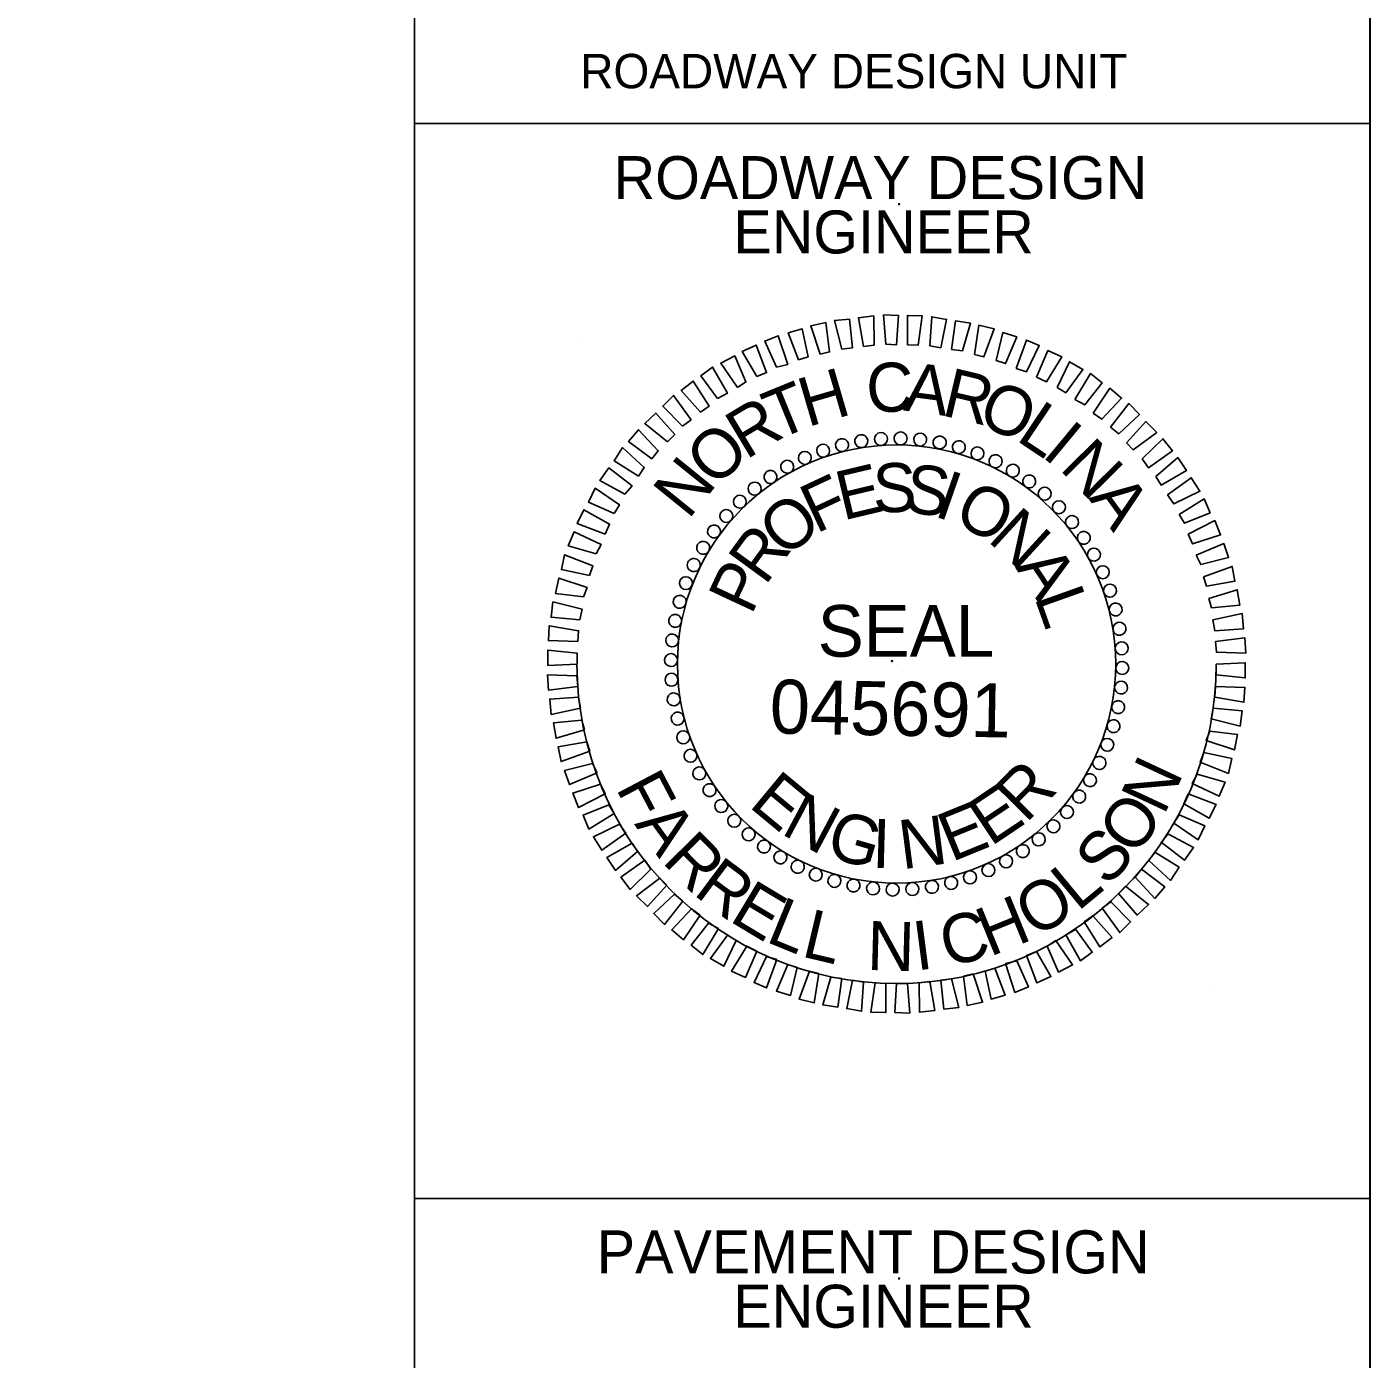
# Model space of a CAD drawing. Extents: x 0 to 3.05, y 0 to 1.83.
# Drawn here: x 2.5366 to 2.7708, y 1.3705 to 1.6029 of the extents above; entities that cross this region are included whole.
import ezdxf

# ---------------------------------------------------------------- set-up
doc = ezdxf.new("R2010")
doc.units = 0
for name, color, linetype in [('Draft_Construction', 7, 'Continuous'), ('Scratch_Level_1', 7, 'Continuous'), ('Scratch_Level_5', 7, 'Continuous'), ('Sheet Border Standard 30in CELL', 7, 'Continuous'), ('Sheet_PE_Note_CELL', 7, 'Continuous'), ('Sheet_Plan_CELL', 7, 'Continuous')]:
    doc.layers.add(name, color=color, linetype=linetype)

msp = doc.modelspace()

# ---------------------------------------------------------------- linework, layer by layer
at = {"layer": 'Draft_Construction'}
for radius, start, end in [(0.03822, 0, 180), (0.05574, 180, 0), (0.03822, 180, 0)]:
    msp.add_arc((2.68825, 1.49175), radius, start, end, dxfattribs=at)
at = {"layer": 'Scratch_Level_1'}
for p, q in [((2.60412, 0.0625), (2.60416, 1.77083)), ((2.77079, 0.0625), (2.77083, 1.77083))]:
    msp.add_line(p, q, dxfattribs=at)
msp.add_lwpolyline([(2.77079, 0.0625), (0.0625, 0.0625), (0.0625, 1.77083), (2.77079, 1.77083)], close=True, dxfattribs=at)
at = {"layer": 'Scratch_Level_5'}
for p, q in [((2.6334, 1.5489), (2.6334, 1.5489)), ((2.7431, 1.4346), (2.7431, 1.4346))]:
    msp.add_line(p, q, dxfattribs=at)
for centre in [(2.6887, 1.57195), (2.68745, 1.49226), (2.68745, 1.49226), (2.68745, 1.49226), (2.68869, 1.38457)]:
    msp.add_circle(centre, 0.0001, dxfattribs=at)
at = {"layer": 'Sheet_PE_Note_CELL'}
for p, q in [((2.67868, 1.52996), (2.67868, 1.52996)), ((2.68213, 1.53058), (2.68213, 1.53058)), ((2.68551, 1.53105), (2.68551, 1.53105)), ((2.68896, 1.53113), (2.68896, 1.53113)), ((2.69241, 1.5309), (2.69241, 1.5309)), ((2.69578, 1.53035), (2.69578, 1.53035)), ((2.67225, 1.52776), (2.67225, 1.52776)), ((2.67538, 1.52901), (2.67538, 1.52901)), ((2.69908, 1.52964), (2.69908, 1.52964)), ((2.70237, 1.52854), (2.70237, 1.52854)), ((2.66919, 1.52619), (2.66919, 1.52619)), ((2.70551, 1.52713), (2.70551, 1.52713)), ((2.70857, 1.52556), (2.70857, 1.52556)), ((2.66621, 1.52439), (2.66621, 1.52439)), ((2.7114, 1.5236), (2.7114, 1.5236)), ((2.66346, 1.52242), (2.66346, 1.52242)), ((2.71414, 1.52148), (2.71414, 1.52148)), ((2.66087, 1.52007), (2.66087, 1.52007)), ((2.71657, 1.51913), (2.71657, 1.51913)), ((2.65852, 1.51764), (2.65852, 1.51764)), ((2.71893, 1.51654), (2.71893, 1.51654)), ((2.6564, 1.51489), (2.6564, 1.51489)), ((2.72089, 1.51379), (2.72089, 1.51379)), ((2.65444, 1.51207), (2.65444, 1.51207)), ((2.65287, 1.50901), (2.65287, 1.50901)), ((2.72269, 1.51081), (2.72269, 1.51081)), ((2.72426, 1.50775), (2.72426, 1.50775)), ((2.65146, 1.50587), (2.65146, 1.50587)), ((2.72552, 1.50462), (2.72552, 1.50462)), ((2.65036, 1.50258), (2.65036, 1.50258)), ((2.64965, 1.49928), (2.64965, 1.49928)), ((2.72646, 1.50132), (2.72646, 1.50132)), ((2.72709, 1.49787), (2.72709, 1.49787)), ((2.6491, 1.49591), (2.6491, 1.49591)), ((2.64887, 1.49245), (2.64887, 1.49245)), ((2.72756, 1.49449), (2.72756, 1.49449)), ((2.68825, 1.49175), (2.68825, 1.49175)), ((2.72764, 1.49104), (2.72764, 1.49104)), ((2.64895, 1.489), (2.64895, 1.489)), ((2.7274, 1.48759), (2.7274, 1.48759)), ((2.64942, 1.48563), (2.64942, 1.48563)), ((2.72685, 1.48422), (2.72685, 1.48422)), ((2.65004, 1.48218), (2.65004, 1.48218)), ((2.72614, 1.48092), (2.72614, 1.48092)), ((2.65099, 1.47888), (2.65099, 1.47888)), ((2.72505, 1.47763), (2.72505, 1.47763)), ((2.65224, 1.47574), (2.65224, 1.47574)), ((2.72363, 1.47449), (2.72363, 1.47449)), ((2.65381, 1.47268), (2.65381, 1.47268)), ((2.72207, 1.47143), (2.72207, 1.47143)), ((2.65561, 1.4697), (2.65561, 1.4697)), ((2.65758, 1.46696), (2.65758, 1.46696)), ((2.7201, 1.4686), (2.7201, 1.4686)), ((2.65993, 1.46437), (2.65993, 1.46437)), ((2.71799, 1.46586), (2.71799, 1.46586)), ((2.66236, 1.46201), (2.66236, 1.46201)), ((2.71563, 1.46343), (2.71563, 1.46343)), ((2.66511, 1.4599), (2.66511, 1.4599)), ((2.71304, 1.46107), (2.71304, 1.46107)), ((2.66793, 1.45793), (2.66793, 1.45793)), ((2.70732, 1.45731), (2.70732, 1.45731)), ((2.7103, 1.45911), (2.7103, 1.45911)), ((2.67099, 1.45637), (2.67099, 1.45637)), ((2.67413, 1.45495), (2.67413, 1.45495)), ((2.70426, 1.45574), (2.70426, 1.45574)), ((2.67742, 1.45386), (2.67742, 1.45386)), ((2.68072, 1.45315), (2.68072, 1.45315)), ((2.68409, 1.4526), (2.68409, 1.4526)), ((2.691, 1.45244), (2.691, 1.45244)), ((2.69437, 1.45291), (2.69437, 1.45291)), ((2.69782, 1.45354), (2.69782, 1.45354)), ((2.70112, 1.45448), (2.70112, 1.45448)), ((2.68754, 1.45236), (2.68754, 1.45236))]:
    msp.add_line(p, q, dxfattribs=at)
for points in [[(2.67491, 1.5458), (2.67327, 1.55075), (2.67593, 1.5513), (2.67656, 1.5462)], [(2.67868, 1.54667), (2.67742, 1.55169), (2.68001, 1.55192), (2.68056, 1.5469)], [(2.68245, 1.54714), (2.68158, 1.55216), (2.68425, 1.55247), (2.68433, 1.54737)], [(2.68637, 1.54753), (2.68598, 1.55263), (2.68856, 1.55255), (2.68825, 1.54745)], [(2.69013, 1.54745), (2.69013, 1.55255), (2.69272, 1.55247), (2.69202, 1.54737)], [(2.69406, 1.54722), (2.69437, 1.55232), (2.69696, 1.55185), (2.69594, 1.5469)], [(2.69782, 1.54659), (2.69853, 1.55161), (2.70112, 1.55122), (2.69971, 1.54635)], [(2.70182, 1.54573), (2.70261, 1.55083), (2.70528, 1.5502), (2.70347, 1.54533)], [(2.6673, 1.54353), (2.66526, 1.54808), (2.66762, 1.54902), (2.66927, 1.544)], [(2.67115, 1.54478), (2.66934, 1.54949), (2.67178, 1.5502), (2.6728, 1.54533)], [(2.70559, 1.54471), (2.70677, 1.54957), (2.7092, 1.54879), (2.70724, 1.54416)], [(2.66385, 1.54188), (2.66134, 1.54627), (2.66377, 1.54737), (2.66558, 1.54259)], [(2.70912, 1.54329), (2.71092, 1.54824), (2.71312, 1.54729), (2.71092, 1.54274)], [(2.71265, 1.5418), (2.71461, 1.54643), (2.71704, 1.54533), (2.71438, 1.54094)], [(2.66048, 1.54), (2.65758, 1.54423), (2.66001, 1.54549), (2.66197, 1.54094)], [(2.71626, 1.54), (2.71838, 1.54447), (2.72073, 1.54314), (2.71775, 1.53906)], [(2.65703, 1.53804), (2.65412, 1.54204), (2.65616, 1.54353), (2.65875, 1.53898)], [(2.71932, 1.53788), (2.72207, 1.54243), (2.7241, 1.54078), (2.72105, 1.53694)], [(2.65404, 1.53568), (2.65067, 1.53945), (2.65279, 1.5411), (2.65554, 1.5367)], [(2.72254, 1.53553), (2.72544, 1.53984), (2.72748, 1.53812), (2.72403, 1.53443)], [(2.65091, 1.53325), (2.64745, 1.5367), (2.64934, 1.53859), (2.6524, 1.53435)], [(2.72552, 1.53309), (2.72873, 1.53717), (2.73062, 1.53529), (2.72701, 1.53192)], [(2.64832, 1.53051), (2.64432, 1.53372), (2.64628, 1.53553), (2.64957, 1.53176)], [(2.64557, 1.52752), (2.64149, 1.53058), (2.64322, 1.53262), (2.64667, 1.52894)], [(2.72834, 1.53035), (2.73171, 1.53404), (2.7336, 1.53215), (2.72952, 1.52909)], [(2.73109, 1.52752), (2.7347, 1.53105), (2.73634, 1.52894), (2.73219, 1.52596)], [(2.64322, 1.52454), (2.63898, 1.52721), (2.64047, 1.52949), (2.64424, 1.52603)], [(2.73344, 1.52446), (2.73729, 1.52776), (2.73878, 1.52548), (2.73438, 1.52297)], [(2.64086, 1.5214), (2.63647, 1.52376), (2.63804, 1.52596), (2.64212, 1.52282)], [(2.73548, 1.52125), (2.73964, 1.52423), (2.74113, 1.52188), (2.73658, 1.51968)], [(2.63898, 1.51803), (2.63451, 1.51999), (2.63569, 1.52242), (2.63992, 1.51952)], [(2.73752, 1.5178), (2.74191, 1.52054), (2.74293, 1.51811), (2.73846, 1.51631)], [(2.63741, 1.51442), (2.63255, 1.51623), (2.63373, 1.51866), (2.6382, 1.51615)], [(2.73909, 1.51442), (2.74372, 1.51678), (2.74474, 1.51427), (2.73987, 1.5127)], [(2.63584, 1.51097), (2.63098, 1.51238), (2.632, 1.51481), (2.63671, 1.51262)], [(2.7405, 1.51073), (2.74529, 1.51277), (2.74615, 1.51034), (2.74129, 1.50909)], [(2.63467, 1.5072), (2.6298, 1.50822), (2.63035, 1.51081), (2.63529, 1.50885)], [(2.74176, 1.50697), (2.74678, 1.50877), (2.74725, 1.50618), (2.74231, 1.50532)], [(2.63365, 1.50344), (2.62878, 1.50407), (2.62933, 1.50673), (2.63427, 1.50509)], [(2.7427, 1.5032), (2.74764, 1.50469), (2.74811, 1.50203), (2.74317, 1.50156)], [(2.63302, 1.49944), (2.628, 1.49991), (2.62831, 1.50258), (2.63341, 1.50132)], [(2.7434, 1.49944), (2.7485, 1.50054), (2.74874, 1.49787), (2.74372, 1.49755)], [(2.63263, 1.49567), (2.62753, 1.49583), (2.62768, 1.49842), (2.63278, 1.49755)], [(2.74388, 1.49567), (2.74898, 1.4963), (2.74913, 1.49363), (2.74403, 1.49379)], [(2.63255, 1.49175), (2.62745, 1.49151), (2.62745, 1.49418), (2.63255, 1.49363)], [(2.74395, 1.49175), (2.74905, 1.49198), (2.74905, 1.48932), (2.74395, 1.48987)], [(2.63263, 1.48783), (2.62753, 1.4872), (2.62737, 1.48987), (2.63247, 1.48971)], [(2.74388, 1.48783), (2.74898, 1.48767), (2.74882, 1.48508), (2.74372, 1.48594)], [(2.6331, 1.48406), (2.628, 1.48296), (2.62776, 1.48563), (2.63278, 1.48594)], [(2.74348, 1.48406), (2.7485, 1.48359), (2.74819, 1.48092), (2.74309, 1.48218)], [(2.6338, 1.48029), (2.62886, 1.4788), (2.62839, 1.48147), (2.63333, 1.48194)], [(2.63474, 1.47653), (2.62972, 1.47472), (2.62925, 1.47731), (2.6342, 1.47818)], [(2.74286, 1.48006), (2.74772, 1.47943), (2.74717, 1.47676), (2.74223, 1.47841)], [(2.74184, 1.47629), (2.7467, 1.47527), (2.74615, 1.47268), (2.74121, 1.47465)], [(2.636, 1.47276), (2.63121, 1.47072), (2.63035, 1.47316), (2.63522, 1.47441)], [(2.74066, 1.47253), (2.74552, 1.47112), (2.7445, 1.46868), (2.7398, 1.47088)], [(2.63741, 1.46908), (2.63278, 1.46672), (2.63176, 1.46923), (2.63663, 1.4708)], [(2.73909, 1.46908), (2.74395, 1.46727), (2.74278, 1.46484), (2.73831, 1.46735)], [(2.63898, 1.4657), (2.63459, 1.46296), (2.63357, 1.46539), (2.63804, 1.46719)], [(2.73752, 1.46547), (2.74199, 1.46351), (2.74082, 1.46107), (2.73658, 1.46398)], [(2.64102, 1.46225), (2.63686, 1.45927), (2.63537, 1.46162), (2.63992, 1.46382)], [(2.73564, 1.46209), (2.74003, 1.45974), (2.73846, 1.45754), (2.73438, 1.46068)], [(2.64306, 1.45903), (2.63922, 1.45574), (2.63773, 1.45801), (2.64212, 1.46052)], [(2.64541, 1.45597), (2.64181, 1.45244), (2.64016, 1.45456), (2.64432, 1.45754)], [(2.73328, 1.45895), (2.73752, 1.45629), (2.73603, 1.45401), (2.73226, 1.45746)], [(2.73093, 1.45597), (2.73501, 1.45291), (2.73328, 1.45087), (2.72983, 1.45456)], [(2.64816, 1.45315), (2.64479, 1.44946), (2.6429, 1.45134), (2.64698, 1.4544)], [(2.72818, 1.45299), (2.73219, 1.44978), (2.73022, 1.44797), (2.72693, 1.45174)], [(2.65099, 1.4504), (2.64777, 1.44632), (2.64589, 1.44821), (2.64949, 1.45158)], [(2.7256, 1.45025), (2.72905, 1.44679), (2.72716, 1.44491), (2.7241, 1.44915)], [(2.65397, 1.44797), (2.65106, 1.44366), (2.64902, 1.44538), (2.65248, 1.44907)], [(2.72246, 1.44781), (2.72583, 1.44405), (2.72371, 1.4424), (2.72097, 1.44679)], [(2.65718, 1.44562), (2.65444, 1.44107), (2.6524, 1.44271), (2.65546, 1.44656)], [(2.71948, 1.44546), (2.72238, 1.44146), (2.72034, 1.43997), (2.71775, 1.44452)], [(2.66024, 1.4435), (2.65812, 1.43903), (2.65577, 1.44036), (2.65875, 1.44444)], [(2.71602, 1.4435), (2.71893, 1.43926), (2.71649, 1.43801), (2.71453, 1.44256)], [(2.66385, 1.44169), (2.66189, 1.43707), (2.65946, 1.43816), (2.66213, 1.44256)], [(2.66738, 1.4402), (2.66558, 1.43526), (2.66338, 1.4362), (2.66558, 1.44075)], [(2.71265, 1.44162), (2.71516, 1.43722), (2.71273, 1.43612), (2.71092, 1.44091)], [(2.67091, 1.43879), (2.66974, 1.43393), (2.6673, 1.43471), (2.66927, 1.43934)], [(2.70535, 1.43871), (2.70716, 1.43401), (2.70473, 1.4333), (2.70371, 1.43816)], [(2.7092, 1.43997), (2.71124, 1.43542), (2.70888, 1.43448), (2.70724, 1.4395)], [(2.67468, 1.43777), (2.67389, 1.43267), (2.67123, 1.4333), (2.67303, 1.43816)], [(2.67868, 1.43691), (2.67797, 1.43189), (2.67538, 1.43228), (2.6768, 1.43714)], [(2.68245, 1.43628), (2.68213, 1.43118), (2.67954, 1.43165), (2.68056, 1.4366)], [(2.68637, 1.43605), (2.68637, 1.43095), (2.68378, 1.43102), (2.68449, 1.43612)], [(2.69013, 1.43597), (2.69053, 1.43087), (2.68794, 1.43095), (2.68825, 1.43605)], [(2.69406, 1.43636), (2.69492, 1.43134), (2.69225, 1.43102), (2.69217, 1.43612)], [(2.69782, 1.43683), (2.69908, 1.43181), (2.69649, 1.43157), (2.69594, 1.4366)], [(2.70159, 1.43769), (2.70324, 1.43275), (2.70057, 1.4322), (2.69994, 1.4373)]]:
    msp.add_lwpolyline(points, close=True, dxfattribs=at)
for centre, major_axis in [((2.68551, 1.53101), (-0.00008, 0.00113)), ((2.68894, 1.5311), (0.00002, 0.00113)), ((2.69236, 1.53089), (0.00012, 0.00112)), ((2.67544, 1.52896), (-0.00037, 0.00107)), ((2.67873, 1.52993), (-0.00027, 0.0011)), ((2.68209, 1.53062), (-0.00018, 0.00112)), ((2.69576, 1.53038), (0.00022, 0.00111)), ((2.6991, 1.52958), (0.00031, 0.00109)), ((2.70235, 1.52849), (0.0004, 0.00105)), ((2.66917, 1.52617), (-0.000548, 0.000988)), ((2.67224, 1.5277), (-0.00046, 0.00103)), ((2.7055, 1.52712), (0.0005, 0.00102)), ((2.66625, 1.52437), (-0.000632, 0.000937)), ((2.70852, 1.52548), (0.000582, 0.000968)), ((2.66349, 1.52233), (-0.000711, 0.000878)), ((2.71138, 1.52359), (0.000664, 0.000914)), ((2.71407, 1.52145), (0.000741, 0.000853)), ((2.66091, 1.52006), (-0.000785, 0.000813)), ((2.71656, 1.51909), (0.000813, 0.000785)), ((2.65855, 1.51757), (-0.000853, 0.000741)), ((2.65641, 1.51488), (-0.000914, 0.000664)), ((2.71883, 1.51651), (0.000878, 0.000711)), ((2.65452, 1.51202), (-0.000968, 0.000582)), ((2.72088, 1.51375), (0.000937, 0.000632)), ((2.72267, 1.51083), (0.000988, 0.000548)), ((2.65288, 1.509), (-0.00102, 0.0005)), ((2.7242, 1.50776), (0.00103, 0.00046)), ((2.65151, 1.50585), (-0.00105, 0.0004)), ((2.72546, 1.50456), (0.00107, 0.00037)), ((2.65042, 1.5026), (-0.00109, 0.00031)), ((2.72644, 1.50127), (0.0011, 0.00027)), ((2.64962, 1.49926), (-0.00111, 0.00022)), ((2.64911, 1.49586), (-0.00112, 0.00012)), ((2.72712, 1.4979), (0.00112, 0.00018)), ((2.72751, 1.49449), (0.00113, 0.00008)), ((2.6489, 1.49244), (-0.00113, 0.00002)), ((2.64899, 1.489), (-0.00113, -0.00008)), ((2.7276, 1.49106), (0.00113, -0.00002)), ((2.72739, 1.48764), (0.00112, -0.00012)), ((2.64938, 1.48559), (-0.00112, -0.00018)), ((2.72688, 1.48424), (0.00111, -0.00022)), ((2.65007, 1.48223), (-0.0011, -0.00027)), ((2.72608, 1.4809), (0.00109, -0.00031)), ((2.65104, 1.47894), (-0.00107, -0.00037)), ((2.72499, 1.47765), (0.00105, -0.0004)), ((2.6523, 1.47574), (-0.00103, -0.00046)), ((2.65383, 1.47267), (-0.000988, -0.000548)), ((2.72362, 1.4745), (0.00102, -0.0005)), ((2.72198, 1.47148), (0.000968, -0.000582)), ((2.65563, 1.46974), (-0.000937, -0.000632)), ((2.72009, 1.46862), (0.000914, -0.000664)), ((2.65767, 1.46698), (-0.000878, -0.000711)), ((2.71795, 1.46593), (0.000853, -0.000741)), ((2.65994, 1.46441), (-0.000813, -0.000785)), ((2.71559, 1.46344), (0.000785, -0.000813)), ((2.66243, 1.46205), (-0.000741, -0.000853)), ((2.71302, 1.46117), (0.000711, -0.000878)), ((2.66512, 1.45991), (-0.000664, -0.000914)), ((2.71026, 1.45912), (0.000632, -0.000937)), ((2.66798, 1.45802), (-0.000582, -0.000968)), ((2.671, 1.45638), (-0.0005, -0.00102)), ((2.70426, 1.4558), (0.00046, -0.00103)), ((2.70733, 1.45733), (0.000548, -0.000988)), ((2.67415, 1.45501), (-0.0004, -0.00105)), ((2.6774, 1.45392), (-0.00031, -0.00109)), ((2.69777, 1.45356), (0.00027, -0.0011)), ((2.70106, 1.45454), (0.00037, -0.00107)), ((2.68074, 1.45312), (-0.00022, -0.00111)), ((2.68414, 1.45261), (-0.00012, -0.00112)), ((2.68756, 1.4524), (-0.00002, -0.00113)), ((2.691, 1.45249), (0.00008, -0.00113)), ((2.69441, 1.45288), (0.00018, -0.00112))]:
    msp.add_ellipse(centre, major_axis=major_axis, ratio=0.999708, dxfattribs=at)
at = {"layer": 'Sheet_Plan_CELL'}
for p, q in [((2.77083, 1.58601), (2.60416, 1.58601)), ((2.77083, 1.58601), (2.60416, 1.58601)), ((2.77074, 1.39851), (2.60408, 1.39851))]:
    msp.add_line(p, q, dxfattribs=at)
for centre in [(2.6887, 1.57195), (2.68745, 1.49226), (2.68745, 1.49226), (2.68745, 1.49226), (2.68869, 1.38457)]:
    msp.add_circle(centre, 0.0001, dxfattribs=at)

# ---------------------------------------------------------------- texts
at = {"layer": 'Sheet Border Standard 30in CELL'}
for s, rotation, p in [('N', 64.9491, (2.73487, 1.4652)), ('F', 297.7948, (2.6392, 1.47013)), ('O', 53.8654, (2.72981, 1.45798)), ('A', 306.1346, (2.64243, 1.46382)), ('R', 314.6222, (2.64717, 1.45725)), ('S', 48.2222, (2.72508, 1.45271)), ('R', 323.2378, (2.65259, 1.45164)), ('L', 39.647, (2.71983, 1.44847)), ('E', 329.0418, (2.65886, 1.44702)), ('O', 30.9582, (2.71234, 1.44384)), ('L', 337.821, (2.66522, 1.44339)), ('H', 22.179, (2.70449, 1.44063)), ('L', 346.666, (2.67145, 1.44078)), ('C', 13.334, (2.69698, 1.43886)), ('N', 358.5168, (2.68303, 1.43839)), ('I', 7.4136, (2.6917, 1.43827))]:
    msp.add_text(s, height=0.00855, rotation=rotation, dxfattribs=at).set_placement(p)
at = {"layer": 'Sheet_PE_Note_CELL'}
for s, height, rotation, p in [('C', 0.00855, 1.4832, (2.68304, 1.53564)), ('A', 0.00855, 352.5864, (2.6893, 1.53599)), ('H', 0.00855, 16.2881, (2.6727, 1.53305)), ('R', 0.00855, 346.666, (2.69589, 1.53517)), ('T', 0.00855, 22.179, (2.66731, 1.53074)), ('O', 0.00855, 337.821, (2.70204, 1.53365)), ('R', 0.00855, 30.9582, (2.66196, 1.5273)), ('L', 0.00855, 326.1343, (2.70889, 1.5309)), ('O', 0.00855, 42.5191, (2.6565, 1.52235)), ('I', 0.00855, 320.353, (2.71338, 1.52808)), ('N', 0.00855, 314.6222, (2.71649, 1.52578)), ('N', 0.00855, 51.0517, (2.65191, 1.5168)), ('E', 0.00855, 13.334, (2.67889, 1.51676)), ('S', 0.00855, 1.4832, (2.68418, 1.51815)), ('S', 0.00855, 352.5864, (2.68938, 1.51832)), ('I', 0.00855, 340.7633, (2.69454, 1.51762)), ('F', 0.00855, 25.1139, (2.67421, 1.51443)), ('O', 0.00855, 331.9594, (2.69785, 1.51666)), ('A', 0.00855, 306.1346, (2.72161, 1.52069)), ('O', 0.00855, 39.647, (2.66882, 1.51006)), ('N', 0.00855, 317.4809, (2.70394, 1.51332)), ('R', 0.00855, 53.8654, (2.66532, 1.50527)), ('P', 0.00855, 64.9491, (2.66291, 1.50011)), ('A', 0.00855, 303.3373, (2.70886, 1.50864)), ('L', 0.00855, 289.6205, (2.71223, 1.5034)), ('045691', 0.009415, 359, (2.66607, 1.47965)), ('R', 0.00855, 45.3778, (2.71081, 1.46386)), ('E', 0.00855, 320.353, (2.66228, 1.46698)), ('N', 0.00855, 331.9594, (2.66788, 1.46221)), ('E', 0.00855, 33.8657, (2.70466, 1.45983)), ('E', 0.00855, 22.179, (2.69782, 1.45716)), ('G', 0.00855, 343.7119, (2.67561, 1.45831)), ('I', 0.00855, 358.5168, (2.68389, 1.4562)), ('N', 0.00855, 7.4136, (2.68922, 1.45593))]:
    msp.add_text(s, height=height, rotation=rotation, dxfattribs=at).set_placement(p)
msp.add_text('SEAL', height=0.009, dxfattribs=at).set_placement((2.67449, 1.49303))
at = {"layer": 'Sheet_Plan_CELL'}
for s, height, p in [('ROADWAY DESIGN UNIT', 0.006, (2.63308, 1.59217)), ('ROADWAY DESIGN', 0.0075, (2.6389, 1.57284)), ('ENGINEER', 0.0075, (2.65979, 1.56336)), ('PAVEMENT DESIGN', 0.0075, (2.63596, 1.38546)), ('ENGINEER', 0.0075, (2.65978, 1.37598))]:
    msp.add_text(s, height=height, rotation=0, dxfattribs=at).set_placement(p)

doc.saveas('drawing.dxf')
